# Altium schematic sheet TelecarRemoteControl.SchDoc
size 190 x 120 mm
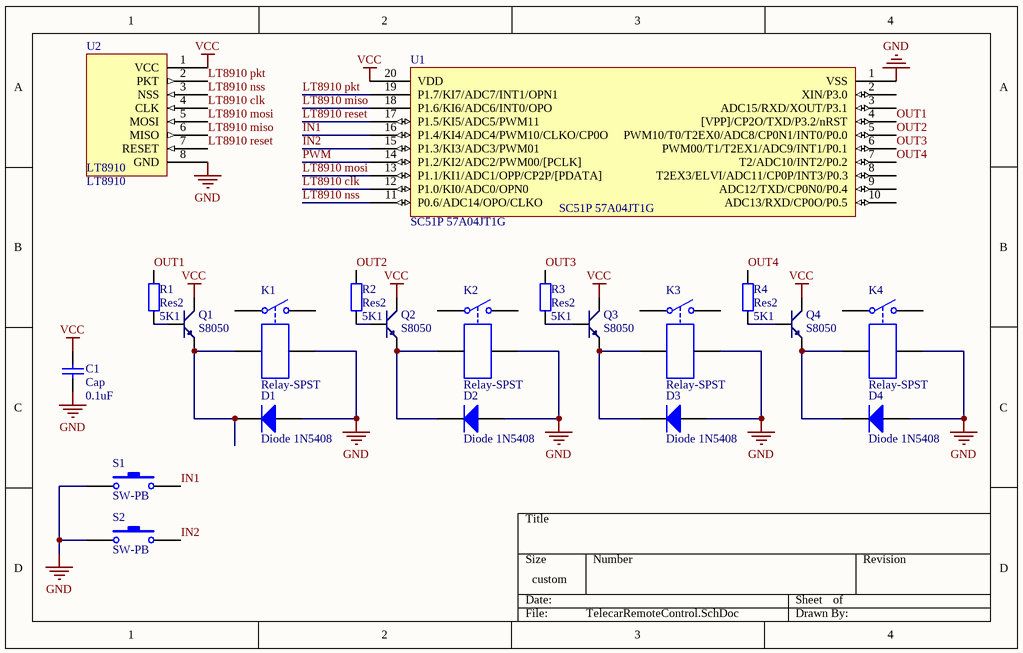
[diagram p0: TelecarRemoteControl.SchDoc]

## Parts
C1  Cap  value 0.1uF  [RAD-0.3]
D1  Diode 1N5408  [DIO18.84-9.6x5.6]
D2  Diode 1N5408  [DIO18.84-9.6x5.6]
D3  Diode 1N5408  [DIO18.84-9.6x5.6]
D4  Diode 1N5408  [DIO18.84-9.6x5.6]
K1  Relay-SPST  [DIP-P4]
K2  Relay-SPST  [DIP-P4]
K3  Relay-SPST  [DIP-P4]
K4  Relay-SPST  [DIP-P4]
Q1  S8050  [SOT-23R]
Q2  S8050  [SOT-23R]
Q3  S8050  [SOT-23R]
Q4  S8050  [SOT-23R]
R1  Res2  value 5K1  [AXIAL-0.4]
R2  Res2  value 5K1  [AXIAL-0.4]
R3  Res2  value 5K1  [AXIAL-0.4]
R4  Res2  value 5K1  [AXIAL-0.4]
S1  SW-PB  [SPST-2]
S2  SW-PB  [SPST-2]
U1  SC51P 57A04JT1G
U2  LT8910

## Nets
GND: C1.1 D1.1(A) D2.1(A) D3.1(A) D4.1(A) K1.4 K2.4 K3.4 K4.4 S1.1 S2.1 U1.1(VSS) U2.8(GND)
VCC: C1.2 Q1.3(C) Q2.3(C) Q3.3(C) Q4.3(C) U1.20(VDD) U2.1(VCC)
IN1: S1.2 U1.16(P1.4/KI4/ADC4/PWM10/CLKO/CP0O)
IN2: S2.2 U1.15(P1.3/KI3/ADC3/PWM01)
LT8910 clk: U1.12(P1.0/KI0/ADC0/OPN0) U2.4(CLK)
LT8910 miso: U1.18(P1.6/KI6/ADC6/INT0/OPO) U2.6(MISO)
LT8910 mosi: U1.13(P1.1/KI1/ADC1/OPP/CP2P/[PDATA]) U2.5(MOSI)
LT8910 nss: U1.11(P0.6/ADC14/OPO/CLKO) U2.3(NSS)
LT8910 pkt: U1.19(P1.7/KI7/ADC7/INT1/OPN1) U2.2(PKT)
LT8910 reset: U1.17(P1.5/KI5/ADC5/PWM11) U2.7(RESET)
OUT1: R1.2 U1.4([VPP]/CP2O/TXD/P3.2/nRST)
OUT2: R2.2 U1.5(PWM10/T0/T2EX0/ADC8/CP0N1/INT0/P0.0)
OUT3: R3.2 U1.6(PWM00/T1/T2EX1/ADC9/INT1/P0.1)
OUT4: R4.2 U1.7(T2/ADC10/INT2/P0.2)
PWM: U1.14(P1.2/KI2/ADC2/PWM00/[PCLK])
NetD1_2: D1.2(K) K1.3 Q1.1(E)
NetD2_2: D2.2(K) K2.3 Q2.1(E)
NetD3_2: D3.2(K) K3.3 Q3.1(E)
NetD4_2: D4.2(K) K4.3 Q4.1(E)
NetQ1_2: Q1.2(B) R1.1
NetQ2_2: Q2.2(B) R2.1
NetQ3_2: Q3.2(B) R3.1
NetQ4_2: Q4.2(B) R4.1

Not connected (* = marked no-connect by the designer): K1 1 2; K2 1 2; K3 1 2; K4 1 2; U1 2(XIN/P3.0) 3(ADC15/RXD/XOUT/P3.1) 8(T2EX3/ELVI/ADC11/CP0P/INT3/P0.3) 9(ADC12/TXD/CP0N0/P0.4) 10(ADC13/RXD/CP0O/P0.5)

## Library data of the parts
C1 = Cap: Capacitor
D1-D4 = Diode 1N5408: 3 Amp Medium Power Silicon Rectifier Diode
K1-K4 = Relay-SPST: Single-Pole Single-Throw Relay
Q1-Q4 = NPN: 8050/BCW846/BCW847
R1-R4 = Res2: Resistor
S1 S2 = SW-PB: Switch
